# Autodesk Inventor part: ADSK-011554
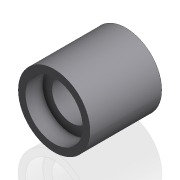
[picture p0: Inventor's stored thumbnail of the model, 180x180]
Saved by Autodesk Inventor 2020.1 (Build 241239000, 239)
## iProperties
Created: 2000-02
Part Number: ADSK-011554
Material: Pearson HRS
Document SubType Name: Modeling
Designer: glanglot
Density: 7.83 g/cm^3
Appearance: Métal - Acier
Mass: 480.277 g
Surface Area: 153.671 cm^2
Volume: 61.338 cm^3
Control State: 0
Checked Out: False
Master: False
Shininess: 0.0
Length Units: 11269
Angle Units: 11279
Time Units: 11290
Mass Units: 11283
Length Display Precision: 3
Angle Display Precision: 2
Compacted: True
Cutlength: 2.06
Material Desc: ROUND,CD 1018,2.0000 DIA
Material_Number: A084581
Dimensions: 50x50x50 mm
Mass: 0,48 kg
Density: 0.0
Volumn: 0.0
Area: 0.0
PropertySet Name: Model Information
Author: glanglot
Revision Number: -
Title: ADSK-011554
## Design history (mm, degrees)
sketch "Skizze2"
  geometry: C1 r 25 at (0, 0) reference; 2 further points
  constraints: 1 coincident
hole "Bohrung2" sketch "Skizze2" diameter "d10" = 27; stored, may be unused: countersink angle "d14" = 90 deg, drill point angle "d16" = 118 deg; dims "d11" = 6, "d12" = 40, "d13" = 12, "d15" = 8
node "Solide1"
  node "Extrusion1" dims "d1" = 50, "d2" = 0
sketch "Sketch1"
  geometry: C1 r 25 at (0, 0); 2 further points
  constraints: 2 coincident, 1 centre point
  dimensions: "d0" = 50 diameter of C1
node "Corps solides"
node "Corps surfaciques"
